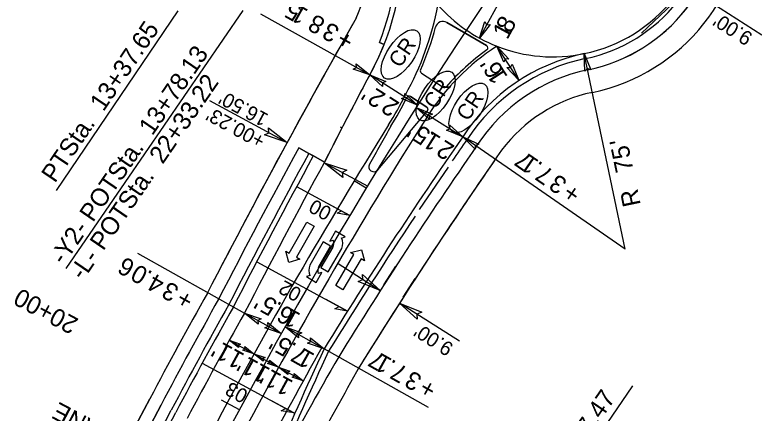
# Model space of a CAD drawing. Extents: x 1975573 to 1977432, y 778300 to 780514.
# Drawn here: x 1976101 to 1976462.7, y 779204.8 to 779399.7 of the extents above; entities that cross this region are included whole.
import ezdxf

# ---------------------------------------------------------------- set-up
doc = ezdxf.new("R2010")
doc.units = 0
for name, color, linetype in [('Prop Conc 2ft 6in Curb and Gutter', 7, 'Continuous'), ('Prop Conc 4in Sidewalk', 7, 'Continuous'), ('Prop Conc 5in Monolithic Keyed In Island', 7, 'Continuous'), ('Prop Conc Drive Radius Type', 7, 'Continuous'), ('Prop Dimension', 7, 'Continuous'), ('Prop Dimension Text', 7, 'Continuous'), ('Prop EOT', 7, 'Continuous'), ('Prop Horizontal Alignment', 7, 'Continuous'), ('Prop Horizontal Alignment Station Label', 7, 'Continuous'), ('Prop Horizontal Alignment Tick Large', 7, 'Continuous'), ('Prop Horizontal Alignment Tick Small', 7, 'Continuous'), ('Prop Lane Arrow CELL', 7, 'Continuous'), ('Prop Lane Lines', 7, 'Continuous'), ('Prop Superelevation  Arrow CELL', 7, 'Continuous'), ('Prop Superelevation Label', 7, 'Continuous'), ('Prop Terminator CELL', 7, 'Continuous'), ('Prop WCC CELL', 7, 'Continuous'), ('Typical Terminator CELL', 7, 'Continuous')]:
    doc.layers.add(name, color=color, linetype=linetype)

# ---------------------------------------------------------------- blocks, each defined once
blk = doc.blocks.new('TERMINATOR')
at = {"layer": 'Typical Terminator CELL'}
blk.add_lwpolyline([(-0.469, 0.081), (0, 0), (-0.471, -0.083), (-0.411, 0)], close=True, dxfattribs=at)

msp = doc.modelspace()

# ---------------------------------------------------------------- linework, layer by layer
at = {"layer": 'Prop Conc 2ft 6in Curb and Gutter'}
for p, q in [((1976279.34, 779386.07), (1976281.69, 779385.22)), ((1976244.81, 779331.85), (1976247.03, 779330.63)), ((1976161.83, 779176.56), (1976177.55, 779206.3))]:
    msp.add_line(p, q, dxfattribs=at)
for centre, radius, start, end in [((1976364.22, 779454.12), 77.5, 281.7976, 1.1936), ((1976165.52, 779431.37), 122.5, 338.3002, 6.5318), ((1976398.72, 779288.93), 91.25, 101.7976, 147.0235), ((1978254.46, 778001.08), 2350.04, 145.30914, 145.61726), ((1979659.02, 777476.1), 3885.95, 151.47429, 152.70695), ((1978254.46, 778001.08), 2350.04, 146.40962, 148.32541), ((1978303.2, 778082.63), 2404.37, 150.73615, 152.1381), ((1978394.15, 778249.43), 2355.79, 155.26703, 156.77372)]:
    msp.add_arc(centre, radius, start, end, dxfattribs=at)
at = {"layer": 'Prop Conc 4in Sidewalk'}
for p, q in [((1976279.34, 779386.07), (1976281.69, 779385.22)), ((1976281.69, 779385.22), (1976279.34, 779386.07)), ((1976279.34, 779386.07), (1976279.34, 779386.07)), ((1976274.59, 779370.32), (1976274.59, 779370.32)), ((1976261, 779344.3), (1976260.38, 779344.69)), ((1976260.38, 779344.69), (1976261.11, 779344.51)), ((1976261, 779344.3), (1976260.38, 779344.69)), ((1976260.38, 779344.69), (1976261.11, 779344.51)), ((1976239.87, 779334.55), (1976244.81, 779331.85)), ((1976244.81, 779331.85), (1976239.87, 779334.55)), ((1976239.87, 779334.55), (1976244.81, 779331.85)), ((1976326.89, 779335.54), (1976326.84, 779335.47)), ((1976247.03, 779330.63), (1976244.81, 779331.85)), ((1976244.81, 779331.85), (1976247, 779330.64)), ((1976247, 779330.64), (1976247.03, 779330.63)), ((1976252.51, 779327.63), (1976247.03, 779330.63)), ((1976151.33, 779182.11), (1976167.05, 779211.85)), ((1976167.05, 779211.85), (1976151.33, 779182.11)), ((1976172.58, 779208.93), (1976156.85, 779179.19)), ((1976156.85, 779179.19), (1976172.58, 779208.93))]:
    msp.add_line(p, q, dxfattribs=at)
for points in [[(1976274.59, 779370.32), (1976274.59, 779370.32)], [(1976326.89, 779335.54), (1976326.84, 779335.47)], [(1976247.03, 779330.63), (1976252.48, 779327.64), (1976252.51, 779327.63)], [(1976269.65, 779227.7), (1976269.72, 779227.66)]]:
    msp.add_lwpolyline(points, dxfattribs=at)
for centre, radius, start, end in [((1976364.22, 779454.12), 83.13, 281.7976, 1.1936), ((1976364.22, 779454.12), 83.12, 281.7976, 1.1936), ((1976364.22, 779454.12), 83.13, 281.7976, 1.1936), ((1976364.22, 779454.12), 94.38, 281.7976, 1.1936), ((1976364.22, 779454.12), 94.38, 281.7976, 1.1936), ((1976170.99, 779441.37), 106.22, 335.9018, 2.4053), ((1976170.99, 779441.37), 106.22, 335.9018, 2.4053), ((1976165.52, 779431.37), 122.5, 338.3002, 6.5318), ((1976165.52, 779431.37), 122.5, 338.3002, 6.5318), ((1979659.02, 777476.1), 3897.83, 150.45742, 152.70395), ((1979659.02, 777476.1), 3897.83, 150.45742, 151.47402), ((1976165.52, 779431.37), 125, 330.7648, 338.3346), ((1976165.52, 779431.37), 125, 330.7648, 338.3346), ((1979659.02, 777476.1), 3897.83, 150.76478, 151.47463), ((1976398.72, 779288.93), 85.63, 101.7976, 147.0235), ((1976398.72, 779288.93), 85.62, 101.7976, 147.0235), ((1976398.72, 779288.93), 85.62, 101.7976, 147.0235), ((1978389.41, 778249.07), 2393.67, 152.06811, 152.76493), ((1978389.41, 778249.07), 2393.67, 152.06811, 152.76493), ((1976398.72, 779288.93), 74.38, 101.7976, 143.2714), ((1976398.72, 779288.93), 74.38, 101.7976, 143.2714), ((1978389.41, 778249.07), 2393.67, 152.77068, 153.21859), ((1978389.41, 778249.07), 2393.67, 152.77068, 153.21859), ((1979659.02, 777476.1), 3897.83, 151.47402, 152.70395), ((1979659.02, 777476.1), 3897.83, 151.47402, 152.70395), ((1979659.02, 777476.1), 3891.58, 151.47402, 152.70553), ((1979659.02, 777476.1), 3891.58, 151.47402, 152.70553), ((1979659.02, 777476.1), 3891.58, 151.47402, 152.70553), ((1978254.46, 778001.08), 2344.42, 145.30706, 148.31707), ((1978254.46, 778001.08), 2344.42, 145.30706, 148.31707), ((1978254.46, 778001.08), 2344.42, 145.30706, 148.31707), ((1978254.46, 778001.08), 2333.17, 145.17716, 148.31707), ((1978254.46, 778001.08), 2333.17, 145.17716, 148.2836), ((1978303.2, 778082.63), 2416.25, 150.741, 152.1381), ((1978303.2, 778082.63), 2416.25, 150.741, 152.1381), ((1978303.2, 778082.63), 2416.25, 150.741, 152.1381), ((1978303.2, 778082.63), 2410, 150.73846, 152.1381), ((1978303.2, 778082.63), 2410, 150.73846, 152.1381), ((1978303.2, 778082.63), 2410, 150.73846, 152.1381), ((1978299.14, 778057.14), 2354.07, 150.0498, 151.55371), ((1978299.14, 778057.14), 2354.07, 150.0498, 151.55371), ((1978299.14, 778057.14), 2354.07, 150.0498, 151.55371), ((1978325.57, 778071.45), 2358.75, 150.64656, 152.96916), ((1978325.57, 778071.45), 2358.75, 150.64656, 152.96916)]:
    msp.add_arc(centre, radius, start, end, dxfattribs=at)
at = {"layer": 'Prop Conc 5in Monolithic Keyed In Island'}
for p, q in [((1976312.34, 779395.96), (1976331.81, 779384.63)), ((1976299.94, 779371.11), (1976310.47, 779364.34)), ((1976294.55, 779359.68), (1976302.57, 779354.58)), ((1976278.54, 779323.78), (1976302.85, 779352.72))]:
    msp.add_line(p, q, dxfattribs=at)
for points in [[(1976331.81, 779384.63), (1976312.34, 779395.96)], [(1976299.94, 779371.11), (1976310.47, 779364.34)], [(1976302.57, 779354.58), (1976294.55, 779359.68)], [(1976278.54, 779323.78), (1976302.85, 779352.72)], [(1976284.94, 779345.16), (1976284.93, 779345.16)]]:
    msp.add_lwpolyline(points, dxfattribs=at)
for centre, radius, start, end in [((1976310.45, 779392.71), 3.75, 59.8207, 165.0666), ((1976310.45, 779392.71), 3.75, 59.8207, 165.0666), ((1976165.52, 779431.37), 146.25, 336.3347, 345.0666), ((1976165.52, 779431.37), 146.25, 336.3347, 345.0666), ((1976398.72, 779288.93), 115, 125.5201, 138.8781), ((1976398.72, 779288.93), 115, 125.5201, 138.8781), ((1976331.18, 779383.55), 1.25, 305.5201, 59.8207), ((1976331.18, 779383.55), 1.25, 305.5201, 59.8207), ((1976300.61, 779372.16), 1.25, 156.3347, 237.2513), ((1976300.61, 779372.16), 1.25, 156.3347, 237.2513), ((1976311.15, 779365.39), 1.25, 237.2513, 318.8781), ((1976311.15, 779365.39), 1.25, 237.2513, 318.8781), ((1976293.88, 779358.62), 1.25, 57.5529, 153.5047), ((1976293.88, 779358.62), 1.25, 57.5529, 153.5047), ((1976139.35, 779435.65), 171.41, 328.1359, 333.5047), ((1976139.35, 779435.65), 171.41, 328.1359, 333.5047), ((1976301.9, 779353.53), 1.25, 319.9706, 57.5529), ((1976301.9, 779353.53), 1.25, 319.9706, 57.5529), ((1978353.31, 778163.55), 2382.1, 150.26177, 150.7748), ((1978353.31, 778163.55), 2382.1, 150.26177, 150.7748), ((1976276.63, 779325.39), 2.5, 151.1771, 319.9706), ((1976276.63, 779325.39), 2.5, 151.1771, 319.9706)]:
    msp.add_arc(centre, radius, start, end, dxfattribs=at)
at = {"layer": 'Prop Conc Drive Radius Type'}
for p, q in [((1976425.61, 779407.97), (1976407.53, 779390.7)), ((1976312.91, 779325.08), (1976298.87, 779304.39))]:
    msp.add_line(p, q, dxfattribs=at)
at = {"layer": 'Prop Dimension'}
for p, q in [((1976434.79, 779410.19), (1976466.33, 779389.91)), ((1976196.31, 779357.77), (1976234.19, 779337.18)), ((1976232.69, 779334.42), (1976232.52, 779334.11)), ((1976273.84, 779315.63), (1976252.31, 779327.33)), ((1976250.81, 779324.57), (1976250.64, 779324.26)), ((1976259.12, 779277.95), (1976279.76, 779264.75)), ((1976281.56, 779267.57), (1976287.43, 779276.73)), ((1976291.04, 779261.5), (1976296.9, 779270.67)), ((1976281.56, 779267.57), (1976281.65, 779267.7)), ((1976318.47, 779239.98), (1976289.24, 779258.69)), ((1976291.04, 779261.5), (1976291.12, 779261.63))]:
    msp.add_line(p, q, dxfattribs=at)
at = {"layer": 'Prop Dimension Text'}
for p, q in [((1976328.24, 779388.31), (1976339.03, 779408.05)), ((1976221.18, 779400.21), (1976274.59, 779370.32)), ((1976347.59, 779367.65), (1976336.76, 779384.33)), ((1976399.54, 779285), (1976379.55, 779380.7)), ((1976298.05, 779355.43), (1976274.59, 779370.32)), ((1976297.39, 779354.39), (1976320.09, 779339.99)), ((1976399.54, 779285), (1976320.09, 779339.99)), ((1976161.1, 779283.1), (1976213.37, 779253.8)), ((1976231.37, 779243.72), (1976213.37, 779253.8)), ((1976233.19, 779246.98), (1976252.26, 779236.26)), ((1976205.94, 779240.44), (1976218, 779233.84)), ((1976218, 779233.84), (1976230.07, 779227.25)), ((1976303.34, 779207.52), (1976252.26, 779236.26)), ((1976230.07, 779227.25), (1976242.13, 779220.65))]:
    msp.add_line(p, q, dxfattribs=at)
at = {"layer": 'Prop EOT'}
msp.add_line((1976164.04, 779175.39), (1976179.76, 779205.13), dxfattribs=at)
for centre, radius, start, end in [((1976364.22, 779454.12), 75, 281.7976, 1.1936), ((1976165.52, 779431.37), 125, 330.7648, 6.5318), ((1976398.72, 779288.93), 93.75, 101.7976, 147.0005), ((1978389.41, 778249.07), 2393.67, 152.06811, 153.21859), ((1978254.46, 778001.08), 2352.54, 145.31005, 148.3291), ((1979659.02, 777476.1), 3883.45, 151.47441, 152.70886), ((1978303.2, 778082.63), 2401.88, 150.73307, 152.1381), ((1978394.15, 778249.43), 2358.29, 155.26335, 156.77128)]:
    msp.add_arc(centre, radius, start, end, dxfattribs=at)
at = {"layer": 'Prop Horizontal Alignment'}
msp.add_arc((1978303.2, 778082.63), 2375, 135.73946, 152.1381, dxfattribs=at)
at = {"layer": 'Prop Horizontal Alignment Station Label'}
for p, q in [((1976121.36, 779313.67), (1976180.99, 779401.56)), ((1976212.49, 779401.79), (1976125.99, 779275.55)), ((1976331.95, 779113.91), (1976403.35, 779218.14))]:
    msp.add_line(p, q, dxfattribs=at)
at = {"layer": 'Prop Horizontal Alignment Tick Large'}
msp.add_line((1976210.89, 779206.4), (1976202.08, 779211.13), dxfattribs=at)
at = {"layer": 'Prop Horizontal Alignment Tick Small'}
msp.add_line((1976272.9, 779314.91), (1976267.56, 779318.15), dxfattribs=at)
at = {"layer": 'Prop Lane Arrow CELL'}
for p, q in [((1976235.2, 779283.07), (1976243.78, 779298.32)), ((1976243.78, 779298.32), (1976247.37, 779296.3)), ((1976247.37, 779296.3), (1976238.8, 779281.05)), ((1976257.83, 779293.79), (1976255.02, 779288.92)), ((1976262.65, 779291), (1976257.83, 779293.79)), ((1976260.82, 779290.47), (1976262.65, 779291)), ((1976251.91, 779288.55), (1976245.31, 779277.13)), ((1976255.48, 779286.48), (1976251.91, 779288.55)), ((1976255.02, 779288.92), (1976256.81, 779289.4)), ((1976235.12, 779278.59), (1976233.57, 779283.99)), ((1976233.57, 779283.99), (1976235.2, 779283.07)), ((1976249.75, 779276.58), (1976255.48, 779286.48)), ((1976256.49, 779285.97), (1976250.76, 779276.07)), ((1976254.33, 779274.01), (1976260.93, 779285.42)), ((1976265.29, 779283.33), (1976270.64, 779284.73)), ((1976270.64, 779284.73), (1976272.06, 779279.3)), ((1976240.43, 779280.13), (1976235.12, 779278.59)), ((1976238.8, 779281.05), (1976240.43, 779280.13)), ((1976257.96, 779267.33), (1976266.91, 779282.37)), ((1976270.45, 779280.26), (1976261.51, 779265.22)), ((1976266.91, 779282.37), (1976265.29, 779283.33)), ((1976272.06, 779279.3), (1976270.45, 779280.26)), ((1976248.35, 779268.8), (1976251.22, 779273.64)), ((1976251.22, 779273.64), (1976249.43, 779273.16)), ((1976250.76, 779276.07), (1976254.33, 779274.01)), ((1976245.42, 779272.09), (1976243.62, 779271.61)), ((1976243.62, 779271.61), (1976248.35, 779268.8)), ((1976261.51, 779265.22), (1976257.96, 779267.33))]:
    msp.add_line(p, q, dxfattribs=at)
for centre, radius, start, end in [((1976252.95, 779288.06), 4.09, 329.9335, 19.5917), ((1976254.82, 779287.84), 6.57, 338.6096, 23.9213), ((1976251.4, 779274.75), 6.57, 158.6096, 203.9213), ((1976253.27, 779274.53), 4.09, 149.9335, 199.5917)]:
    msp.add_arc(centre, radius, start, end, dxfattribs=at)
at = {"layer": 'Prop Lane Lines'}
for centre, radius, start, end in [((1976165.52, 779431.37), 145, 330.7648, 349.3113), ((1976364.22, 779454.12), 75, 221.447, 248.5228), ((1976398.72, 779288.93), 113.75, 123.0053, 147.6498), ((1976364.22, 779454.12), 75, 248.5228, 281.7976), ((1976139.35, 779435.65), 170.16, 328.1359, 333.8095), ((1978303.2, 778082.63), 2368.12, 147.64977, 152.13802), ((1978303.2, 778082.63), 2381.88, 147.97195, 152.1381), ((1979659.02, 777476.1), 3877.2, 151.47472, 152.70886), ((1978303.2, 778082.63), 2395.62, 150.73307, 152.1381), ((1978303.2, 778082.63), 2354.38, 150.64291, 152.13802)]:
    msp.add_arc(centre, radius, start, end, dxfattribs=at)
at = {"layer": 'Prop Superelevation  Arrow CELL'}
for p, q in [((1976264.85, 779301.55), (1976254.31, 779307.28)), ((1976263.78, 779254.74), (1976253.24, 779260.47)), ((1976237.48, 779204.91), (1976226.94, 779210.64))]:
    msp.add_line(p, q, dxfattribs=at)
for points in [[(1976264.85, 779301.55), (1976258.63, 779302.66), (1976260.79, 779303.76)], [(1976263.78, 779254.74), (1976257.56, 779255.85), (1976259.72, 779256.95)], [(1976237.48, 779204.91), (1976231.26, 779206.01), (1976233.42, 779207.11)]]:
    msp.add_lwpolyline(points, close=True, dxfattribs=at)
at = {"layer": 'Prop Superelevation Label'}
for p, q in [((1976238.8, 779315.71), (1976264.85, 779301.55)), ((1976219.37, 779278.88), (1976263.78, 779254.74)), ((1976192.69, 779229.25), (1976237.48, 779204.91))]:
    msp.add_line(p, q, dxfattribs=at)
at = {"layer": 'Prop Terminator CELL'}
for points in [[(1976333.56, 779395.02), (1976328.24, 779388.31), (1976330.99, 779396.48), (1976331.79, 779394.81)], [(1976340.14, 779376.46), (1976336.76, 779384.33), (1976342.64, 779378.03), (1976340.79, 779378.12)], [(1976379.85, 779372.15), (1976379.55, 779380.7), (1976382.76, 779372.7), (1976381.07, 779373.45)], [(1976267.94, 779375.71), (1976274.59, 779370.32), (1976266.46, 779373.15), (1976268.13, 779373.94)], [(1976344.21, 779375.52), (1976347.59, 779367.65), (1976341.71, 779373.95), (1976343.55, 779373.86)], [(1976280.94, 779364.57), (1976274.59, 779370.32), (1976282.56, 779367.04), (1976280.85, 779366.35)], [(1976291.71, 779361.17), (1976298.05, 779355.43), (1976290.08, 779358.71), (1976291.8, 779359.39)], [(1976303.74, 779348.64), (1976297.39, 779354.39), (1976305.36, 779351.11), (1976303.65, 779350.42)], [(1976313.75, 779345.74), (1976320.09, 779339.99), (1976312.13, 779343.27), (1976313.84, 779343.96)], [(1976326.2, 779334), (1976320.09, 779339.99), (1976327.92, 779336.4), (1976326.18, 779335.78)], [(1976220.02, 779248.41), (1976213.37, 779253.8), (1976221.51, 779250.96), (1976219.83, 779250.18)], [(1976224.72, 779249.11), (1976231.37, 779243.72), (1976223.23, 779246.56), (1976224.9, 779247.34)], [(1976239.84, 779241.58), (1976233.19, 779246.98), (1976241.33, 779244.13), (1976239.65, 779243.35)], [(1976210.41, 779236.89), (1976205.94, 779240.44), (1976211.38, 779238.6), (1976210.27, 779238.07)], [(1976245.62, 779241.66), (1976252.26, 779236.26), (1976244.13, 779239.11), (1976245.81, 779239.89)], [(1976213.53, 779237.39), (1976218, 779233.84), (1976212.56, 779235.68), (1976213.67, 779236.21)], [(1976222.47, 779230.29), (1976218, 779233.84), (1976223.45, 779232.01), (1976222.34, 779231.47)], [(1976225.6, 779230.79), (1976230.07, 779227.25), (1976224.63, 779229.08), (1976225.74, 779229.61)], [(1976234.54, 779223.7), (1976230.07, 779227.25), (1976235.51, 779225.41), (1976234.4, 779224.88)], [(1976237.66, 779224.2), (1976242.13, 779220.65), (1976236.69, 779222.49), (1976237.8, 779223.02)]]:
    msp.add_lwpolyline(points, close=True, dxfattribs=at)
at = {"layer": 'Prop WCC CELL'}
for centre in [(1976289.77, 779380.28), (1976306.87, 779359.98), (1976322.91, 779354.17)]:
    msp.add_ellipse(centre, major_axis=(7.87, 11.6), ratio=0.462467, dxfattribs=at)

# ---------------------------------------------------------------- block references
at = {"layer": 'Prop Dimension'}
for p, xscale, yscale, rotation in [((1976234.19, 779337.18), 24.499999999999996, 24.5, -28.52528312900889), ((1976252.31, 779327.33), 24.499999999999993, 24.499999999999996, 151.47471687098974), ((1976279.76, 779264.75), 24.499999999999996, 24.500000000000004, -32.61264179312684), ((1976289.24, 779258.69), 24.499999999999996, 24.499999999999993, 147.38735820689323)]:
    msp.add_blockref('TERMINATOR', p, dxfattribs=dict(at, xscale=xscale, yscale=yscale, rotation=rotation))

# ---------------------------------------------------------------- texts
for s, rotation, p in [("9.00'", 147.3874, (1976462.49, 779390.08)), ("16.50'", 151.4747, (1976225.53, 779350.77)), ("+00.23'", 151.4747, (1976224.16, 779340.08)), ("9.00'", 147.3874, (1976316.13, 779238.15))]:
    msp.add_text(s, height=7, rotation=rotation, dxfattribs=at).set_placement(p)
at = {"layer": 'Prop Dimension Text'}
for s, height, rotation, p in [('DETAIL OF ROUNDABOUT @ -Y2-', 25, 55.5983, (1976426.44, 779079.33)), ('5', 8.75, 150.7648, (1976242.08, 779403.56)), ('1', 8.75, 150.7648, (1976245.08, 779401.88)), ('8', 8.75, 150.7648, (1976253.5, 779397.17)), ('8', 8.75, 61.3342, (1976343.54, 779390.21)), ('3', 8.75, 150.7648, (1976260.47, 779393.26)), ('1', 8.75, 61.3342, (1976341.89, 779387.19)), ('+', 8.75, 150.7648, (1976267.68, 779389.23)), ("'", 8.75, 123.0053, (1976336.71, 779378.21)), ('6', 8.75, 123.0053, (1976340.54, 779372.32)), ('1', 8.75, 123.0053, (1976342.42, 779369.43)), ('2', 8.75, 147.5942, (1976283, 779360.77)), ("'", 8.75, 147.5942, (1976276.37, 779364.98)), ('2', 8.75, 147.5942, (1976289.63, 779356.57)), ('5', 8.75, 147.6238, (1976305.1, 779342.68)), ("'", 8.75, 147.6238, (1976298.7, 779346.73)), ('1', 8.75, 147.6238, (1976309.98, 779339.58)), ('.', 8.75, 147.6238, (1976307.07, 779341.42)), ('2', 8.75, 147.6238, (1976316.62, 779335.37)), ("'", 8.75, 101.7976, (1976400.8, 779337.47)), ('5', 8.75, 101.7976, (1976402.35, 779330.05)), ('7', 8.75, 145.31, (1976355.03, 779330.05)), ('1', 8.75, 145.31, (1976357.86, 779328.09)), ('.', 8.75, 145.31, (1976359.79, 779326.76)), ('7', 8.75, 101.7976, (1976403.7, 779323.58)), ('7', 8.75, 145.31, (1976365.22, 779322.99)), ('3', 8.75, 145.31, (1976371.79, 779318.45)), ('+', 8.75, 145.31, (1976378.59, 779313.74)), ('R', 8.75, 101.7976, (1976407.21, 779306.78)), ('6', 8.75, 150.7331, (1976160.47, 779278.43)), ('0', 8.75, 150.7331, (1976166.84, 779274.86)), ('.', 8.75, 150.7331, (1976168.89, 779273.72)), ('4', 8.75, 150.7331, (1976175.02, 779270.28)), ('3', 8.75, 150.7331, (1976181.99, 779266.38)), ('+', 8.75, 150.7331, (1976189.2, 779262.34)), ("'", 8.75, 150.7331, (1976223.53, 779263.15)), ('5', 8.75, 150.7331, (1976230.14, 779259.45)), ('.', 8.75, 150.7331, (1976232.19, 779258.31)), ('6', 8.75, 150.7331, (1976238.32, 779254.87)), ('1', 8.75, 150.7331, (1976241.32, 779253.19)), ('5', 8.75, 150.6429, (1976237.43, 779239.58)), ("11'", 8.75, 151.3418, (1976213.94, 779233.5)), ("'", 8.75, 150.6429, (1976230.83, 779243.29)), ('7', 8.75, 150.6429, (1976245.24, 779235.19)), ('.', 8.75, 150.6429, (1976239.47, 779238.43)), ('1', 8.75, 150.6429, (1976248.24, 779233.5)), ('7', 8.75, 150.6429, (1976283.06, 779232.72)), ('1', 8.75, 150.6429, (1976286.06, 779231.03)), ("11'", 8.75, 151.3418, (1976226.51, 779226.4)), ('.', 8.75, 150.6429, (1976288.1, 779229.88)), ("11'", 8.75, 151.3418, (1976237.71, 779220.3)), ('7', 8.75, 150.6429, (1976293.86, 779226.64)), ('3', 8.75, 150.6429, (1976300.83, 779222.72)), ('+', 8.75, 150.6429, (1976308.03, 779218.67)), ('LANE', 8.75, 152.1381, (1976149.54, 779196.22))]:
    msp.add_text(s, height=height, rotation=rotation, dxfattribs=at).set_placement(p)
at = {"layer": 'Prop Horizontal Alignment Station Label'}
for s, rotation, p in [('PTSta.  13+37.65', 55.8441, (1976120.63, 779317.05)), ('-Y2- POTSta.  13+78.13', 55.5601, (1976124.89, 779276.91)), ('-L- POTSta.  22+33.22', 55.5601, (1976134.37, 779269.4)), ('20+00', 151.7602, (1976132.68, 779250.7)), ('-L- PCSta.  19+87.47', 55.5805, (1976332.9, 779121.32))]:
    msp.add_text(s, height=8.75, rotation=rotation, dxfattribs=at).set_placement(p)
at = {"layer": 'Prop Superelevation Label'}
for s, p in [('00', (1976256.6, 779304.82)), ('02', (1976241.85, 779265.13)), ('03', (1976215.67, 779215.45))]:
    msp.add_text(s, height=7, rotation=151.4747, dxfattribs=at).set_placement(p)
at = {"layer": 'Prop WCC CELL'}
for p in [(1976289.52, 779373.33), (1976306.62, 779353.03), (1976322.65, 779347.22)]:
    msp.add_text('CR', height=7.5, rotation=55.8441, dxfattribs=at).set_placement(p)

doc.saveas('drawing.dxf')
